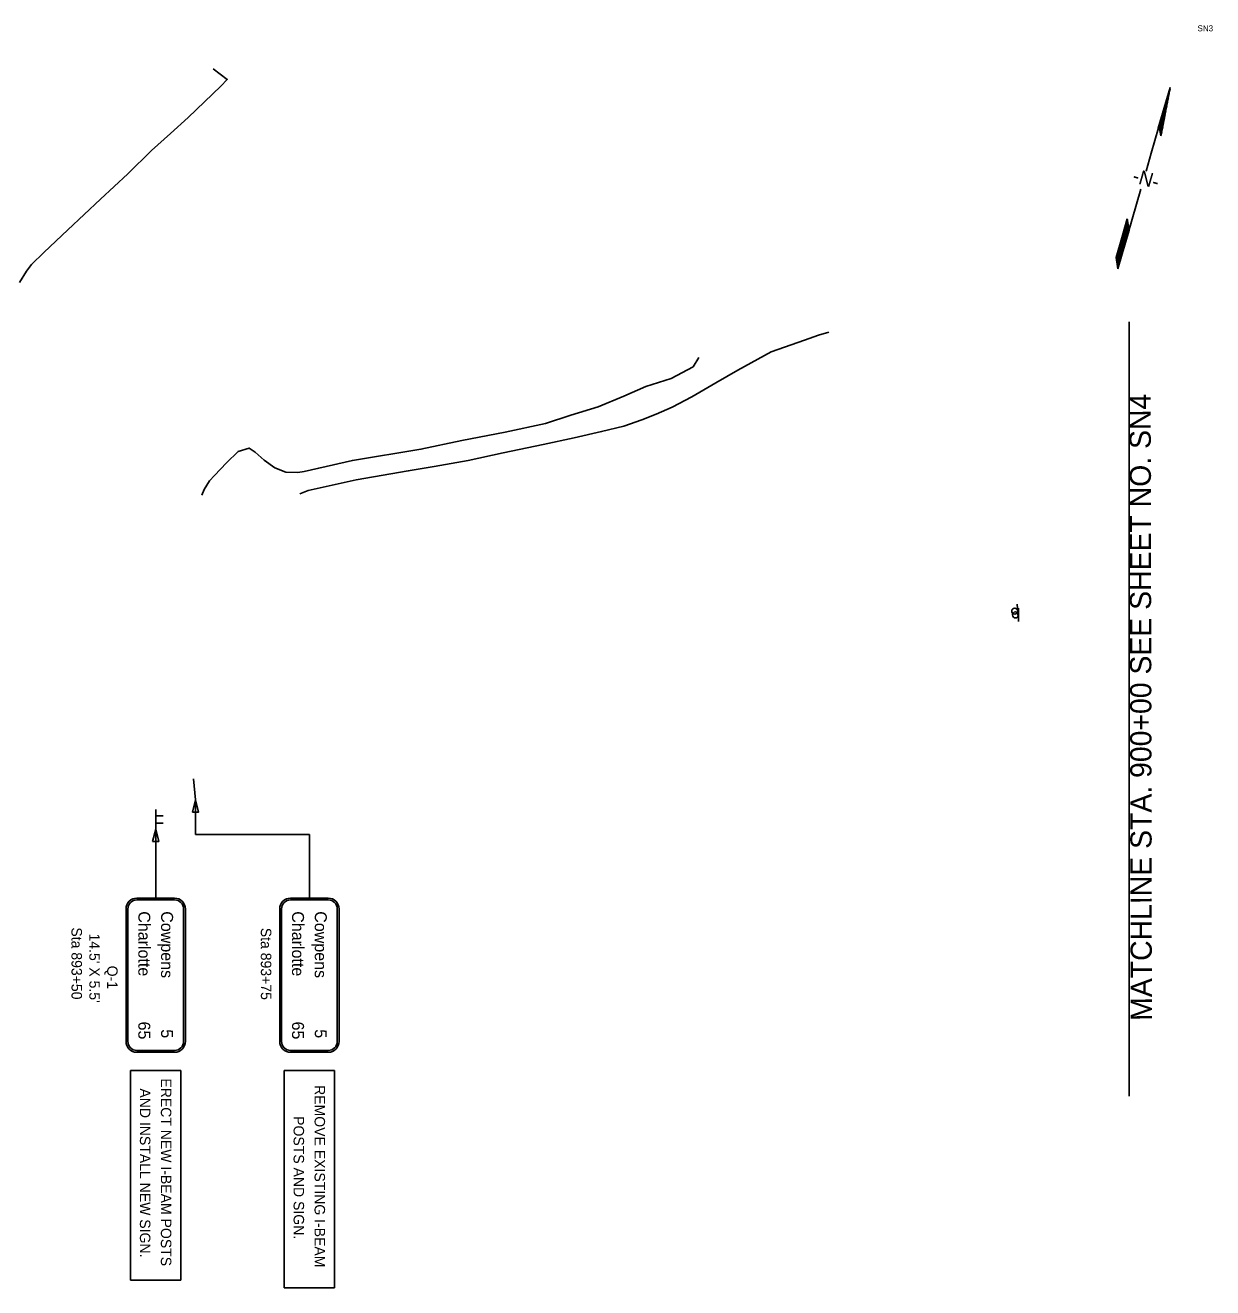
# Model space of a CAD drawing. Extents: x 1738774 to 1740360, y 1165523 to 1166492.
# Drawn here: x 1739567 to 1740360, y 1165649 to 1166492 of the extents above; entities that cross this region are included whole.
import ezdxf

# ---------------------------------------------------------------- set-up
doc = ezdxf.new("R2010")
doc.units = 0
for name, color, linetype in [('RD_EX_Driveway', 7, 'Continuous'), ('RD_EX_Road', 7, 'Continuous'), ('RD_SHT_MatchLine', 7, 'Continuous'), ('RD_SHT_TX', 7, 'Continuous'), ('RD_Sketch1', 7, 'Continuous'), ('SN_P_Signs', 7, 'Continuous')]:
    doc.layers.add(name, color=color, linetype=linetype)

msp = doc.modelspace()

# ---------------------------------------------------------------- linework, layer by layer
at = {"layer": 'RD_EX_Driveway'}
for points in [[(1739749.93, 1166179.22), (1739755.54, 1166181.3), (1739787.65, 1166188.51), (1739822.37, 1166194.5), (1739839.66, 1166197.49), (1739862.29, 1166201.48), (1739885.73, 1166206.52), (1739912.46, 1166212.14), (1739933.08, 1166216.64), (1739951.44, 1166220.67), (1739966.22, 1166224.24), (1739978.4, 1166228.6), (1739987.84, 1166232.44), (1739998.67, 1166236.95), (1740011.76, 1166243.82), (1740027.78, 1166253.16), (1740042.52, 1166261.7), (1740064.64, 1166274.03), (1740086.91, 1166281.81), (1740096.36, 1166285.06), (1740103.18, 1166287.08)], [(1739684.63, 1166178.36), (1739686.16, 1166182.13), (1739689.75, 1166187.89), (1739693.04, 1166191.33), (1739700.95, 1166199.86), (1739708.83, 1166207.49), (1739716.1, 1166209.69), (1739720.05, 1166206.91), (1739726.17, 1166201.65), (1739733.32, 1166196.62), (1739740.64, 1166193.66), (1739748.65, 1166193.4), (1739752.79, 1166193.98), (1739762.64, 1166196.39), (1739785.04, 1166201.44), (1739830.84, 1166208.91), (1739858.1, 1166214.67), (1739887.03, 1166220.4), (1739913.99, 1166226.01), (1739930.88, 1166231.59), (1739949.13, 1166237.13), (1739966.31, 1166244.4), (1739980.99, 1166250.89), (1739997.84, 1166256.12), (1740012.5, 1166263.84), (1740016.27, 1166270.09)]]:
    msp.add_lwpolyline(points, dxfattribs=at)
at = {"layer": 'RD_EX_Road'}
msp.add_lwpolyline([(1739692.17, 1166463), (1739701.5, 1166455.81), (1739697.11, 1166451.26), (1739675.4, 1166430.45), (1739663.62, 1166419.74), (1739650.94, 1166408.41), (1739635.07, 1166392.69), (1739616.84, 1166375.93), (1739594.98, 1166355.41), (1739579.04, 1166340.37), (1739570.71, 1166332.37), (1739567.51, 1166327.79), (1739562.69, 1166320.3)], dxfattribs=at)
at = {"layer": 'RD_SHT_MatchLine'}
msp.add_lwpolyline([(1740303.73, 1165777), (1740303.73, 1166044.04), (1740303.73, 1166294.08)], dxfattribs=at)
at = {"layer": 'RD_Sketch1'}
for p, q in [((1740331.16, 1166450.54), (1740323.12, 1166423.27)), ((1740324.94, 1166418.09), (1740331.16, 1166450.54)), ((1740323.35, 1166423.45), (1740318.46, 1166406.5)), ((1740323.83, 1166424.25), (1740324.94, 1166418.09)), ((1740318.46, 1166406.5), (1740315, 1166394.49)), ((1740311.54, 1166382.49), (1740305.77, 1166362.47)), ((1740305.77, 1166362.47), (1740296.24, 1166329.44)), ((1740299.29, 1166351.67), (1740302.47, 1166362.68)), ((1740302.47, 1166362.68), (1740303.65, 1166355.13)), ((1740295.06, 1166336.99), (1740299.29, 1166351.67)), ((1740296.24, 1166329.44), (1740295.06, 1166336.99))]:
    msp.add_line(p, q, dxfattribs=at)
for points in [[(1740323.43, 1166423.69), (1740331.14, 1166450.44)], [(1740323.56, 1166423.87), (1740330.98, 1166449.62)], [(1740323.69, 1166424.05), (1740330.83, 1166448.8)], [(1740323.82, 1166424.23), (1740330.67, 1166447.97)], [(1740323.86, 1166424.09), (1740330.51, 1166447.15)], [(1740323.89, 1166423.92), (1740330.35, 1166446.33)], [(1740323.92, 1166423.75), (1740330.19, 1166445.5)], [(1740323.3, 1166423.51), (1740327.95, 1166439.65)], [(1740323.95, 1166423.58), (1740330.04, 1166444.68)], [(1740323.98, 1166423.41), (1740329.88, 1166443.86)], [(1740324.01, 1166423.24), (1740329.72, 1166443.03)], [(1740324.04, 1166423.07), (1740329.56, 1166442.21)], [(1740324.08, 1166422.9), (1740329.41, 1166441.39)], [(1740324.11, 1166422.73), (1740329.25, 1166440.56)], [(1740324.14, 1166422.56), (1740329.09, 1166439.74)], [(1740324.17, 1166422.39), (1740328.93, 1166438.92)], [(1740324.2, 1166422.22), (1740328.77, 1166438.09)], [(1740324.23, 1166422.05), (1740328.62, 1166437.27)], [(1740324.26, 1166421.88), (1740328.46, 1166436.45)], [(1740324.29, 1166421.71), (1740328.3, 1166435.62)], [(1740324.32, 1166421.54), (1740328.14, 1166434.8)], [(1740324.35, 1166421.37), (1740327.98, 1166433.98)], [(1740324.38, 1166421.2), (1740327.83, 1166433.16)], [(1740324.41, 1166421.03), (1740327.67, 1166432.33)], [(1740324.44, 1166420.86), (1740327.51, 1166431.51)], [(1740324.47, 1166420.69), (1740327.35, 1166430.69)], [(1740324.5, 1166420.52), (1740327.2, 1166429.86)], [(1740324.53, 1166420.35), (1740327.04, 1166429.04)], [(1740323.17, 1166423.33), (1740324.32, 1166427.32)], [(1740324.56, 1166420.18), (1740326.88, 1166428.22)], [(1740324.59, 1166420.01), (1740326.72, 1166427.39)], [(1740324.62, 1166419.84), (1740326.56, 1166426.57)], [(1740324.65, 1166419.67), (1740326.41, 1166425.75)], [(1740324.68, 1166419.5), (1740326.25, 1166424.92)], [(1740324.71, 1166419.33), (1740326.09, 1166424.1)], [(1740324.75, 1166419.16), (1740325.93, 1166423.28)], [(1740324.78, 1166418.99), (1740325.77, 1166422.45)], [(1740324.81, 1166418.82), (1740325.62, 1166421.63)], [(1740324.84, 1166418.65), (1740325.46, 1166420.81)], [(1740324.87, 1166418.48), (1740325.3, 1166419.99)], [(1740324.9, 1166418.31), (1740325.14, 1166419.16)], [(1740324.93, 1166418.14), (1740324.99, 1166418.34)], [(1740295.08, 1166336.84), (1740302.49, 1166362.53)], [(1740295.11, 1166336.67), (1740302.52, 1166362.35)], [(1740295.14, 1166336.49), (1740302.54, 1166362.17)], [(1740295.17, 1166336.31), (1740302.57, 1166361.99)], [(1740295.19, 1166336.13), (1740302.6, 1166361.82)], [(1740295.22, 1166335.95), (1740302.63, 1166361.64)], [(1740295.25, 1166335.77), (1740302.66, 1166361.46)], [(1740295.28, 1166335.59), (1740302.68, 1166361.28)], [(1740295.31, 1166335.42), (1740302.71, 1166361.1)], [(1740295.33, 1166335.24), (1740302.74, 1166360.92)], [(1740295.36, 1166335.06), (1740302.77, 1166360.74)], [(1740295.39, 1166334.88), (1740302.8, 1166360.57)], [(1740295.42, 1166334.7), (1740302.82, 1166360.39)], [(1740295.45, 1166334.52), (1740302.85, 1166360.21)], [(1740295.47, 1166334.34), (1740302.88, 1166360.03)], [(1740295.5, 1166334.17), (1740302.91, 1166359.85)], [(1740295.53, 1166333.99), (1740302.94, 1166359.67)], [(1740295.56, 1166333.81), (1740302.96, 1166359.49)], [(1740295.59, 1166333.63), (1740302.99, 1166359.32)], [(1740295.61, 1166333.45), (1740303.02, 1166359.14)], [(1740295.64, 1166333.27), (1740303.05, 1166358.96)], [(1740295.67, 1166333.09), (1740303.08, 1166358.78)], [(1740295.7, 1166332.92), (1740303.1, 1166358.6)], [(1740295.73, 1166332.74), (1740303.13, 1166358.42)], [(1740295.75, 1166332.56), (1740303.16, 1166358.25)], [(1740295.78, 1166332.38), (1740303.19, 1166358.07)], [(1740295.81, 1166332.2), (1740303.22, 1166357.89)], [(1740295.84, 1166332.02), (1740303.24, 1166357.71)], [(1740295.87, 1166331.84), (1740303.27, 1166357.53)], [(1740295.89, 1166331.67), (1740303.3, 1166357.35)], [(1740295.92, 1166331.49), (1740303.33, 1166357.17)], [(1740295.95, 1166331.31), (1740303.36, 1166357)], [(1740295.98, 1166331.13), (1740303.38, 1166356.82)], [(1740296.01, 1166330.95), (1740303.41, 1166356.64)], [(1740296.03, 1166330.77), (1740303.44, 1166356.46)], [(1740296.06, 1166330.59), (1740303.47, 1166356.28)], [(1740296.09, 1166330.42), (1740303.5, 1166356.1)], [(1740296.12, 1166330.24), (1740303.52, 1166355.92)], [(1740296.15, 1166330.06), (1740303.55, 1166355.75)], [(1740296.17, 1166329.88), (1740303.58, 1166355.57)], [(1740296.2, 1166329.7), (1740303.61, 1166355.39)], [(1740296.23, 1166329.52), (1740303.64, 1166355.21)]]:
    msp.add_lwpolyline(points, dxfattribs=at)
at = {"layer": 'SN_P_Signs'}
for p, q in [((1740229.63, 1166096.5), (1740228.98, 1166105.47)), ((1740229.91, 1166093.84), (1740229.72, 1166102.84)), ((1739680.35, 1165974.92), (1739679.04, 1165988.91)), ((1739680.35, 1165951.79), (1739680.35, 1165974.92)), ((1739653.73, 1165955.27), (1739653.73, 1165968.31)), ((1739653.73, 1165964.2), (1739658.72, 1165964.2)), ((1739653.73, 1165959.18), (1739658.72, 1165959.18)), ((1739653.73, 1165909.22), (1739653.73, 1165955.27)), ((1739680.35, 1165951.79), (1739756.36, 1165951.79)), ((1739756.36, 1165909.22), (1739756.36, 1165951.79)), ((1739672.33, 1165902.02), (1739672.33, 1165813.55)), ((1739673.53, 1165902.02), (1739673.53, 1165813.55)), ((1739774.96, 1165902.02), (1739774.96, 1165813.55)), ((1739776.16, 1165902.02), (1739776.16, 1165813.55)), ((1739636.93, 1165654.11), (1739636.93, 1165794.13)), ((1739636.93, 1165794.13), (1739670.54, 1165794.13)), ((1739670.54, 1165794.13), (1739670.54, 1165654.11)), ((1739739.55, 1165649.11), (1739739.55, 1165794.13)), ((1739739.55, 1165794.13), (1739773.16, 1165794.13)), ((1739773.16, 1165794.13), (1739773.16, 1165649.11)), ((1739670.54, 1165654.11), (1739636.93, 1165654.11)), ((1739773.16, 1165649.11), (1739739.55, 1165649.11))]:
    msp.add_line(p, q, dxfattribs=at)
for points in [[(1739678.3, 1165966.72), (1739680.35, 1165974.92), (1739682.4, 1165966.72)], [(1739651.68, 1165947.07), (1739653.73, 1165955.27), (1739655.79, 1165947.07)]]:
    msp.add_lwpolyline(points, close=True, dxfattribs=at)
for points in [[(1739641.13, 1165909.22), (1739666.33, 1165909.22)], [(1739641.13, 1165908.02), (1739666.33, 1165908.02)], [(1739743.76, 1165909.22), (1739768.96, 1165909.22)], [(1739743.76, 1165908.02), (1739768.96, 1165908.02)], [(1739633.93, 1165813.55), (1739633.93, 1165902.02)], [(1739635.13, 1165813.55), (1739635.13, 1165902.02)], [(1739736.56, 1165813.55), (1739736.56, 1165902.02)], [(1739737.76, 1165813.55), (1739737.76, 1165902.02)], [(1739666.33, 1165807.55), (1739641.13, 1165807.55)], [(1739666.33, 1165806.35), (1739641.13, 1165806.35)], [(1739768.96, 1165807.55), (1739743.76, 1165807.55)], [(1739768.96, 1165806.35), (1739743.76, 1165806.35)]]:
    msp.add_lwpolyline(points, dxfattribs=at)
for centre in [(1740227.29, 1166100.85), (1740227.79, 1166098.32)]:
    msp.add_circle(centre, 2, dxfattribs=at)
for centre, radius, start, end in [((1739641.13, 1165902.02), 7.2, 89.99999, 179.99999), ((1739641.13, 1165902.02), 6, 89.99999, 179.99999), ((1739666.33, 1165902.02), 7.2, 359.99999, 89.99999), ((1739666.33, 1165902.02), 6, 359.99999, 89.99999), ((1739743.76, 1165902.02), 7.2, 89.99999, 179.99999), ((1739743.76, 1165902.02), 6, 89.99999, 179.99999), ((1739768.96, 1165902.02), 7.2, 359.99999, 89.99999), ((1739768.96, 1165902.02), 6, 359.99999, 89.99999), ((1739641.13, 1165813.55), 7.2, 179.99999, 269.99999), ((1739641.13, 1165813.55), 6, 179.99999, 269.99999), ((1739666.33, 1165813.55), 6, 269.99999, 359.99999), ((1739666.33, 1165813.55), 7.2, 269.99999, 359.99999), ((1739743.76, 1165813.55), 7.2, 179.99999, 269.99999), ((1739743.76, 1165813.55), 6, 179.99999, 269.99999), ((1739768.96, 1165813.55), 6, 269.99999, 359.99999), ((1739768.96, 1165813.55), 7.2, 269.99999, 359.99999)]:
    msp.add_arc(centre, radius, start, end, dxfattribs=at)

# ---------------------------------------------------------------- texts
at = {"layer": 'RD_SHT_TX'}
msp.add_text('SN3', height=4, dxfattribs=at).set_placement((1740349.35, 1166487.94))
msp.add_text('MATCHLINE STA. 900+00 SEE SHEET NO. SN4', height=14.1726, rotation=90.11236, dxfattribs=at).set_placement((1740318.94, 1165827.33))
at = {"layer": 'RD_Sketch1'}
msp.add_text('-N-', height=9.548, rotation=343.91524, dxfattribs=at).set_placement((1740305.23, 1166387.43))
at = {"layer": 'SN_P_Signs'}
for s, height, rotation, p in [('Charlotte', 8, 269.99999, (1739642.13, 1165900.46)), ('Cowpens', 8, 269.99999, (1739657.33, 1165900.46)), ('Charlotte', 8, 269.99999, (1739744.76, 1165900.46)), ('Cowpens', 8, 269.99999, (1739759.96, 1165900.46)), ('Sta 893+50', 7, 270.00008, (1739597.51, 1165889.7)), ('Sta 893+75', 7, 270.00008, (1739723.94, 1165889.43)), ("14.5' X 5.5'", 7, 270.00008, (1739609.41, 1165885.62)), ('Q-1', 7, 270.00008, (1739621.31, 1165864.13)), ('65', 8, 269.99999, (1739642.13, 1165826.82)), ('65', 8, 269.99999, (1739744.76, 1165826.82)), ('5', 8, 269.99999, (1739657.33, 1165821.67)), ('5', 8, 269.99999, (1739759.96, 1165821.67)), ('ERECT NEW I-BEAM POSTS', 6.9998, 270.00008, (1739657.18, 1165788.9)), ('AND INSTALL NEW SIGN.', 6.9998, 270.00008, (1739643.18, 1165782.2)), ('REMOVE EXISTING I-BEAM', 6.9998, 270.00008, (1739759.8, 1165784.38)), ('POSTS AND SIGN. ', 6.9998, 270.00008, (1739745.8, 1165763.68))]:
    msp.add_text(s, height=height, rotation=rotation, dxfattribs=at).set_placement(p)

doc.saveas('drawing.dxf')
